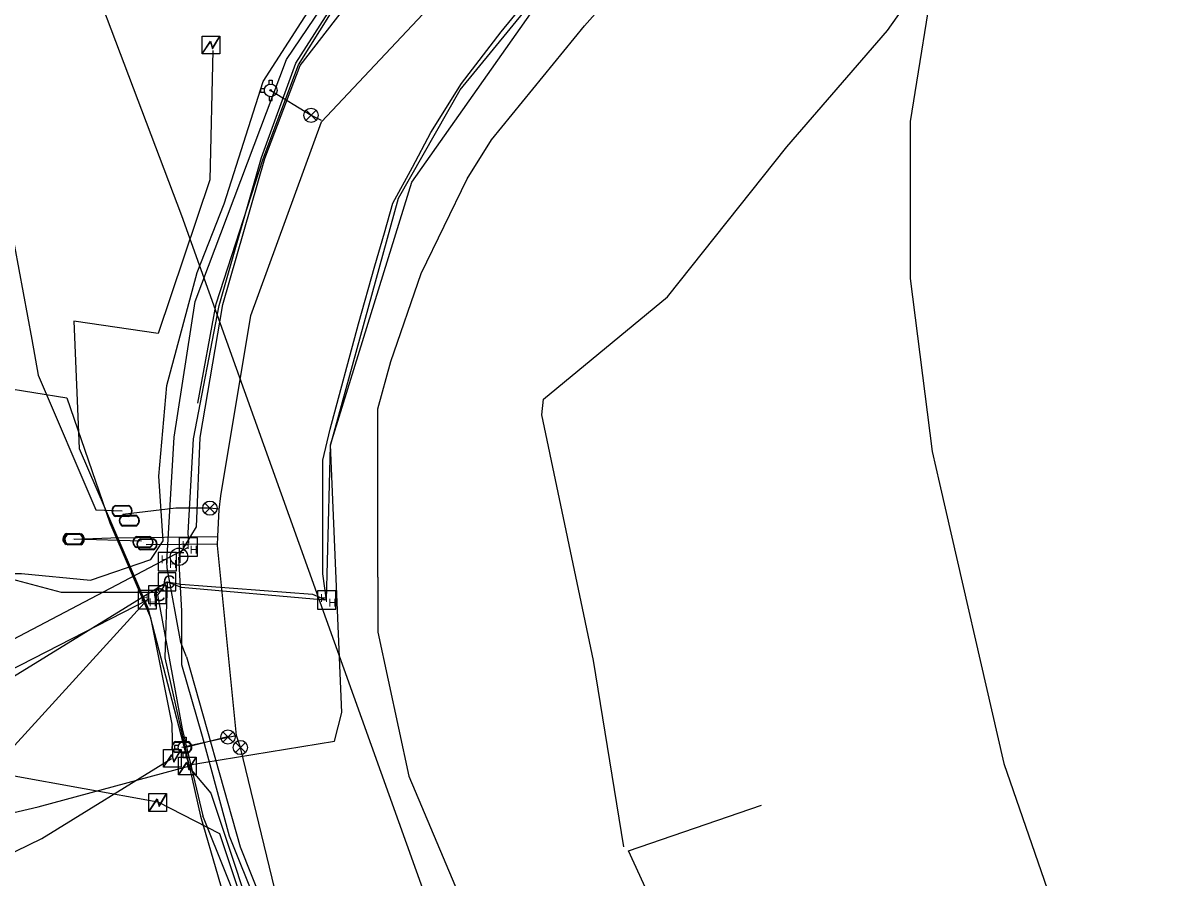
# Model space of a CAD drawing. Extents: x 2070721 to 2083340, y 729290 to 737883.
# Drawn here: x 2080183.4 to 2080544.7, y 734144.7 to 734411.8 of the extents above; entities that cross this region are included whole.
import ezdxf

# ---------------------------------------------------------------- set-up
doc = ezdxf.new("R2010")
doc.units = 0
for name, color, linetype in [('Exist Utilities Other Unknown UG SUE LOS B', 7, 'Continuous'), ('Exist Utilities Power Transformer CELL', 7, 'Continuous'), ('Exist Utilities Power UG Cable SUE LOS B', 7, 'Continuous'), ('Exist Utilities Power UG Cable SUE LOS C', 7, 'Continuous'), ('Exist Utilities Telephone Hand Hole CELL', 7, 'Continuous'), ('Exist Utilities Telephone Manhole CELL', 7, 'Continuous'), ('Exist Utilities Telephone UG Cable SUE LOS C', 7, 'Continuous'), ('Exist Utilities Telephone UG Conduit SUE LOS B', 7, 'Continuous'), ('Exist Utilities Telephone UG FO SUE LOS B', 7, 'Continuous'), ('Exist Utilities Telephone UG FO SUE LOS C', 7, 'Continuous'), ('Exist Utilities TV Hand Hole CELL', 7, 'Continuous'), ('Exist Utilities TV Pedestal CELL', 7, 'Continuous'), ('Exist Utilities TV UG Cable SUE LOS B', 7, 'Continuous'), ('Exist Utilities TV UG Cable SUE LOS C', 7, 'Continuous'), ('Exist Utilities TV UG FO Cable SUE LOS B', 7, 'Continuous'), ('Exist Utilities TV UG FO Cable SUE LOS C', 7, 'Continuous'), ('Exist Utilities Water Fire Hydrant CELL', 7, 'Continuous'), ('Exist Utilities Water Meter CELL', 7, 'Continuous'), ('Exist Utilities Water UG Line SUE LOS B', 7, 'Continuous'), ('Exist Utilities Water Valve CELL', 7, 'Continuous')]:
    doc.layers.add(name, color=color, linetype=linetype)

msp = doc.modelspace()

# ---------------------------------------------------------------- linework, layer by layer
at = {"layer": 'Exist Utilities Other Unknown UG SUE LOS B'}
msp.add_lwpolyline([(2080237.92, 734293.08), (2080243.61, 734324.09), (2080258.34, 734369.36), (2080269.39, 734398.77), (2080286.02, 734425.45), (2080301.91, 734450.14), (2080317.89, 734467.75), (2080331.23, 734480.5), (2080381.43, 734521.31), (2080414.27, 734537.75), (2080416.02, 734538.24)], dxfattribs=at)
at = {"layer": 'Exist Utilities Power Transformer CELL'}
for p, q in [((2080242.08, 734405.14), (2080242.08, 734405.14)), ((2080230.02, 734182.19), (2080230.02, 734182.19)), ((2080234.72, 734179.83), (2080234.72, 734179.83)), ((2080225.45, 734168.4), (2080225.45, 734168.4))]:
    msp.add_line(p, q, dxfattribs=at)
for points in [[(2080239.24, 734407.75), (2080244.79, 734407.75), (2080244.79, 734402.2), (2080239.24, 734402.2)], [(2080227.17, 734184.81), (2080232.73, 734184.81), (2080232.73, 734179.25), (2080227.17, 734179.25)], [(2080231.88, 734182.44), (2080237.43, 734182.44), (2080237.43, 734176.89), (2080231.88, 734176.89)], [(2080222.61, 734171.01), (2080228.16, 734171.01), (2080228.16, 734165.46), (2080222.61, 734165.46)]]:
    msp.add_lwpolyline(points, close=True, dxfattribs=at)
for points in [[(2080239.24, 734402.2), (2080241.88, 734406.14), (2080242.51, 734403.93), (2080244.79, 734407.75)], [(2080239.31, 734402.2), (2080241.88, 734405.93), (2080242.47, 734403.75), (2080244.79, 734407.6)], [(2080227.17, 734179.25), (2080229.82, 734183.2), (2080230.45, 734180.99), (2080232.73, 734184.81)], [(2080227.24, 734179.25), (2080229.82, 734182.99), (2080230.4, 734180.81), (2080232.73, 734184.65)], [(2080231.88, 734176.89), (2080234.52, 734180.84), (2080235.15, 734178.63), (2080237.43, 734182.44)], [(2080231.95, 734176.89), (2080234.52, 734180.63), (2080235.11, 734178.44), (2080237.43, 734182.29)], [(2080222.61, 734165.46), (2080225.25, 734169.4), (2080225.88, 734167.19), (2080228.16, 734171.01)], [(2080222.68, 734165.46), (2080225.25, 734169.19), (2080225.84, 734167.01), (2080228.16, 734170.86)]]:
    msp.add_lwpolyline(points, dxfattribs=at)
at = {"layer": 'Exist Utilities Power UG Cable SUE LOS B'}
for points in [[(2080234.71, 734179.89), (2080280.62, 734187.44), (2080282.92, 734196.34), (2080279.43, 734280.03), (2080304.76, 734362.13), (2080356.55, 734435.67), (2080374.96, 734451.44)], [(2080370.98, 734154.39), (2080361.51, 734212.64), (2080345.43, 734289.41), (2080345.93, 734294.31), (2080384.7, 734326.31), (2080421.96, 734373.11), (2080453.41, 734409.54), (2080468.5, 734430.99)], [(2080468.5, 734430.99), (2080460.53, 734381.1), (2080460.53, 734331.98), (2080467.37, 734277.9), (2080469.6, 734267.89), (2080489.8, 734180.39), (2080505.22, 734135.47), (2080514.45, 734118.41)], [(2080242.66, 734403.28), (2080241.67, 734362.84), (2080225.56, 734314.83), (2080199.19, 734318.7), (2080200.86, 734278.87), (2080222.27, 734229.12), (2080235.32, 734178.97)], [(2080111.69, 734308.48), (2080119.26, 734311.71), (2080135.22, 734307.67), (2080154.56, 734303.8), (2080166.01, 734301.54), (2080176.37, 734298.05), (2080196.98, 734294.69), (2080210.47, 734255.68), (2080223.19, 734226.04), (2080229.85, 734192.73), (2080230.05, 734182.23)], [(2079937.52, 734192.32), (2079957.19, 734181.58), (2080020.32, 734166.12), (2080064.52, 734156.78), (2080106.22, 734147.77), (2080188.06, 734166.87), (2080235.43, 734179.74)], [(2080225.42, 734168.33), (2080179.4, 734176.66), (2080141.16, 734176.91), (2080123.55, 734183.66)], [(2080133.41, 734166.28), (2080133.92, 734165.53), (2080152.74, 734139.3), (2080189.19, 734157.01), (2080229.69, 734182.03)], [(2080234.72, 734179.83), (2080241.98, 734171.12), (2080276.22, 734068.16), (2080293.76, 734026.09), (2080325.21, 734006.15), (2080360.35, 733978.15), (2080376.41, 733964.84), (2080394.21, 733967.31), (2080427.72, 733990.11), (2080441.72, 734003.26), (2080444.29, 734010.08)], [(2080443.09, 734017.91), (2080429.26, 734056.79), (2080388.33, 734118.62), (2080372.45, 734153.12), (2080414.03, 734167.36)]]:
    msp.add_lwpolyline(points, dxfattribs=at)
at = {"layer": 'Exist Utilities Power UG Cable SUE LOS C'}
for points in [[(2080186.05, 734475.29), (2080232.86, 734351.65), (2080379.47, 733942.04), (2080251.03, 733903.89)], [(2080225.45, 734168.4), (2080244.65, 734158.51), (2080253.95, 734130.69), (2080282.75, 734048.52), (2080295.34, 734028.75), (2080340.63, 733997.06), (2080355.06, 733989.84), (2080368.99, 733977.25), (2080380.73, 733968.31), (2080393.86, 733970.13), (2080428.86, 733995.36), (2080444.29, 734010.08)]]:
    msp.add_lwpolyline(points, dxfattribs=at)
at = {"layer": 'Exist Utilities Telephone Hand Hole CELL'}
for p, q in [((2080232.12, 734250.92), (2080232.12, 734245.2)), ((2080237.84, 734250.92), (2080232.12, 734250.92)), ((2080237.84, 734245.2), (2080237.84, 734250.92)), ((2080234.98, 734248.06), (2080234.98, 734248.06)), ((2080225.59, 734246.39), (2080225.59, 734240.67)), ((2080231.31, 734246.39), (2080225.59, 734246.39)), ((2080228.45, 734243.53), (2080228.45, 734243.53)), ((2080231.31, 734240.67), (2080231.31, 734246.39)), ((2080232.12, 734245.2), (2080237.84, 734245.2)), ((2080225.59, 734240.67), (2080231.31, 734240.67)), ((2080219.31, 734234.5), (2080219.31, 734228.77)), ((2080225.03, 734234.5), (2080219.31, 734234.5)), ((2080225.03, 734228.77), (2080225.03, 734234.5)), ((2080219.31, 734228.77), (2080225.03, 734228.77)), ((2080222.17, 734231.63), (2080222.17, 734231.63))]:
    msp.add_line(p, q, dxfattribs=at)
at = {"layer": 'Exist Utilities Telephone Manhole CELL'}
msp.add_circle((2080232.05, 734245.04), 2.72, dxfattribs=at)
at = {"layer": 'Exist Utilities Telephone UG Cable SUE LOS C'}
for points in [[(2080179.48, 734239.75), (2080182.79, 734239.75), (2080204.44, 734237.74), (2080223.27, 734244.14), (2080227.06, 734249.97), (2080225.75, 734270.22), (2080228.23, 734298.53), (2080237.75, 734333.83), (2080246.14, 734355.32), (2080258.39, 734393.6), (2080274.22, 734418.19), (2080320.87, 734477.75), (2080344.36, 734497.56), (2080358.62, 734490.18), (2080387.98, 734454.99)], [(2080294.22, 734238.68), (2080294.22, 734255.9), (2080294.22, 734291.26), (2080298.27, 734306.08), (2080307.66, 734333.57), (2080322.1, 734363.11), (2080329.68, 734375.34), (2080358.78, 734411), (2080382.14, 734437.37), (2080392.23, 734444.72), (2080389.38, 734455.18)], [(2080291.1, 734070.12), (2080273.08, 734096.26), (2080264.86, 734115.07), (2080247.85, 734157.71), (2080239.41, 734188.85), (2080232.9, 734211.26), (2080232.9, 734228.12), (2080231.97, 734244.9)], [(2080294.22, 734238.68), (2080294.22, 734221.46), (2080303.86, 734176.45), (2080326.14, 734123.68), (2080343.11, 734086.02), (2080369.71, 734062.6), (2080410.57, 734039.8), (2080423.78, 734028.65), (2080421.38, 734022.96), (2080402.46, 733993.71), (2080385.13, 733965.19), (2080355.27, 733912.59), (2080339.2, 733870.84), (2080335.53, 733861.67)]]:
    msp.add_lwpolyline(points, dxfattribs=at)
at = {"layer": 'Exist Utilities Telephone UG Conduit SUE LOS B'}
msp.add_lwpolyline([(2080232.24, 734245.67), (2080237.5, 734254.36), (2080238.66, 734282.35), (2080245.75, 734323.83), (2080258.86, 734369.55), (2080269.86, 734398.57), (2080309.08, 734449.32), (2080323.63, 734464.88), (2080355.41, 734492.16), (2080379.52, 734509.8), (2080416.03, 734529.49), (2080502.71, 734562.3), (2080573.96, 734587.12), (2080616.57, 734603.22), (2080677.16, 734624.99), (2080749, 734651.22), (2080815.57, 734674.3), (2080861.11, 734690.56), (2080923.26, 734714.15), (2080934.26, 734720.97)], dxfattribs=at)
at = {"layer": 'Exist Utilities Telephone UG FO SUE LOS B'}
for points in [[(2080235.11, 734249.36), (2080234.94, 734252.48), (2080236.58, 734281.87), (2080244.62, 734323.58), (2080257.8, 734369.84), (2080268.59, 734399.28), (2080285.42, 734425.78), (2080306.49, 734446.52), (2080318.99, 734464.89), (2080332.07, 734479.26), (2080365.28, 734504.24), (2080415, 734536.31), (2080432.75, 734546.34), (2080471.85, 734557.5), (2080502.31, 734568.65), (2080534.18, 734580.2), (2080570.94, 734591.77), (2080576.66, 734593.81), (2080717.24, 734648.01)], [(2080228.28, 734243.43), (2080230.55, 734282.39), (2080237.1, 734324.84), (2080265.61, 734400.42), (2080300.19, 734451.55), (2080329.83, 734482.91), (2080380.99, 734522.11), (2080413.6, 734539.64), (2080433.63, 734544.47), (2080470.56, 734559.5), (2080533.58, 734581.77), (2080652.68, 734625.4)], [(2079959.83, 734188.33), (2080105.23, 734179.43), (2080123.21, 734189.25), (2080234.98, 734248.06)], [(2080234.38, 734213.72), (2080232.6, 734218.25), (2080228.35, 734241.54), (2080228.28, 734243.43)], [(2080234.38, 734213.72), (2080232.6, 734218.25), (2080228.35, 734241.54), (2080228.28, 734243.43)], [(2080222.28, 734231.61), (2080174.53, 734207.04), (2080146.45, 734195)], [(2080234.38, 734213.72), (2080251.15, 734154.39), (2080272, 734101.95), (2080285.47, 734081.3)]]:
    msp.add_lwpolyline(points, dxfattribs=at)
at = {"layer": 'Exist Utilities Telephone UG FO SUE LOS C'}
msp.add_line((2080147.53, 734149.79), (2080222.17, 734231.63), dxfattribs=at)
msp.add_lwpolyline([(2080225.43, 734233.87), (2080195.29, 734233.87), (2080178.12, 734238.44)], dxfattribs=at)
at = {"layer": 'Exist Utilities TV Hand Hole CELL'}
msp.add_line((2080278.21, 734231.5), (2080278.21, 734231.5), dxfattribs=at)
msp.add_lwpolyline([(2080275.34, 734228.63), (2080281.09, 734228.63), (2080281.09, 734234.38), (2080275.34, 734234.38), (2080275.34, 734228.63)], dxfattribs=at)
at = {"layer": 'Exist Utilities TV Pedestal CELL'}
for p, q in [((2080228.33, 734237.2), (2080228.33, 734237.2)), ((2080225.3, 734233.17), (2080225.3, 734233.17))]:
    msp.add_line(p, q, dxfattribs=at)
for points in [[(2080225.55, 734234.43), (2080231.1, 734234.43), (2080231.1, 734239.97), (2080225.55, 734239.97), (2080225.55, 734234.43)], [(2080222.52, 734230.39), (2080228.07, 734230.39), (2080228.07, 734235.94), (2080222.52, 734235.94), (2080222.52, 734230.39)]]:
    msp.add_lwpolyline(points, dxfattribs=at)
at = {"layer": 'Exist Utilities TV UG Cable SUE LOS B'}
for points in [[(2080278.08, 734231.48), (2080277, 734239.67), (2080277, 734275.25), (2080279.3, 734284.9), (2080288.08, 734317.87), (2080293.24, 734335.92), (2080296.25, 734346.26), (2080298.88, 734355.59), (2080304.96, 734366.83), (2080310.77, 734377.58), (2080320.31, 734392.98), (2080332.74, 734409.06), (2080345.11, 734424.32), (2080353.93, 734435.35), (2080365.15, 734446.1), (2080376.65, 734455.86), (2080394.1, 734462.75), (2080415.44, 734468.86), (2080444.8, 734480.86), (2080490.14, 734502.72), (2080540.63, 734520.42), (2080564.59, 734528.02)], [(2080228.33, 734237.2), (2080232.7, 734235.49), (2080277.64, 734231.55)]]:
    msp.add_lwpolyline(points, dxfattribs=at)
at = {"layer": 'Exist Utilities TV UG Cable SUE LOS C'}
msp.add_lwpolyline([(2080228.33, 734237.2), (2080227.59, 734213.41), (2080238.77, 734164.01), (2080249.82, 734126.01), (2080269.26, 734089.95), (2080305.09, 734043.13), (2080320.73, 734021.92)], dxfattribs=at)
at = {"layer": 'Exist Utilities TV UG FO Cable SUE LOS B'}
for points in [[(2080232.67, 734236.44), (2080273.72, 734233.3), (2080278.08, 734231.48), (2080279.38, 734279.77), (2080300.6, 734357.07), (2080319.92, 734390.91), (2080356.3, 734435.5), (2080369.79, 734448.44), (2080390.27, 734462.8), (2080376.9, 734455.01)], [(2080227.31, 734235.69), (2080225.31, 734233.11), (2080233, 734191.29), (2080239.52, 734164.02)], [(2080321.01, 734022.31), (2080305.36, 734043.56), (2080269.25, 734089.82), (2080239.52, 734164.02)]]:
    msp.add_lwpolyline(points, dxfattribs=at)
at = {"layer": 'Exist Utilities TV UG FO Cable SUE LOS C'}
msp.add_lwpolyline([(2079959.93, 734183.76), (2080108.68, 734169.55), (2080152.84, 734190.77), (2080228.33, 734237.2), (2080232.67, 734236.44)], dxfattribs=at)
at = {"layer": 'Exist Utilities Water Fire Hydrant CELL'}
for p, q in [((2080260.69, 734390.79), (2080260.69, 734390.79)), ((2080233.8, 734185.5), (2080233.8, 734185.5))]:
    msp.add_line(p, q, dxfattribs=at)
for points in [[(2080258.78, 734391.3), (2080257.49, 734391.3), (2080257.49, 734390.28), (2080258.78, 734390.28)], [(2080260.18, 734392.7), (2080260.18, 734393.99), (2080261.2, 734393.99), (2080261.2, 734392.68)], [(2080260.18, 734388.88), (2080260.18, 734387.59), (2080261.2, 734387.59), (2080261.2, 734388.9)], [(2080231.89, 734186.01), (2080230.6, 734186.01), (2080230.6, 734184.99), (2080231.89, 734184.99)], [(2080233.29, 734187.41), (2080233.29, 734188.7), (2080234.31, 734188.7), (2080234.31, 734187.39)], [(2080233.29, 734183.59), (2080233.29, 734182.3), (2080234.31, 734182.3), (2080234.31, 734183.61)]]:
    msp.add_lwpolyline(points, dxfattribs=at)
for centre, radius in [((2080260.69, 734390.79), 1.98), ((2080260.69, 734390.79), 0.243), ((2080233.8, 734185.5), 1.98), ((2080233.8, 734185.5), 0.243)]:
    msp.add_circle(centre, radius, dxfattribs=at)
at = {"layer": 'Exist Utilities Water Meter CELL'}
for p, q in [((2080214.25, 734259.36), (2080214.25, 734259.36)), ((2080216.51, 734256.31), (2080216.51, 734256.31)), ((2080198.9, 734250.57), (2080198.9, 734250.57)), ((2080199.4, 734250.49), (2080199.4, 734250.49)), ((2080220.81, 734249.62), (2080220.81, 734249.62)), ((2080222.04, 734248.94), (2080222.04, 734248.94)), ((2080232.95, 734185.55), (2080232.95, 734185.55))]:
    msp.add_line(p, q, dxfattribs=at)
for points in [[(2080216.29, 734257.8), (2080212.19, 734257.8)], [(2080216.29, 734257.66), (2080212.19, 734257.66)], [(2080212.21, 734261.06), (2080216.29, 734261.06)], [(2080212.21, 734260.92), (2080216.29, 734260.92)], [(2080214.47, 734258.01), (2080218.55, 734258.01)], [(2080214.47, 734257.87), (2080218.55, 734257.87)], [(2080218.55, 734254.75), (2080214.45, 734254.75)], [(2080218.55, 734254.61), (2080214.45, 734254.61)], [(2080196.86, 734252.27), (2080200.94, 734252.27)], [(2080196.86, 734252.13), (2080200.94, 734252.13)], [(2080197.36, 734252.19), (2080201.44, 734252.19)], [(2080197.36, 734252.05), (2080201.44, 734252.05)], [(2080218.77, 734251.32), (2080222.84, 734251.32)], [(2080218.77, 734251.18), (2080222.84, 734251.18)], [(2080220, 734250.64), (2080224.08, 734250.64)], [(2080220, 734250.5), (2080224.08, 734250.5)], [(2080200.94, 734249.01), (2080196.84, 734249.01)], [(2080200.94, 734248.87), (2080196.84, 734248.87)], [(2080201.44, 734248.93), (2080197.34, 734248.93)], [(2080201.44, 734248.79), (2080197.34, 734248.79)], [(2080222.84, 734248.06), (2080218.74, 734248.06)], [(2080222.84, 734247.92), (2080218.74, 734247.92)], [(2080224.08, 734247.38), (2080219.98, 734247.38)], [(2080224.08, 734247.24), (2080219.98, 734247.24)], [(2080230.91, 734187.25), (2080234.99, 734187.25)], [(2080230.91, 734187.11), (2080234.99, 734187.11)], [(2080234.99, 734183.99), (2080230.89, 734183.99)], [(2080234.99, 734183.85), (2080230.89, 734183.85)]]:
    msp.add_lwpolyline(points, dxfattribs=at)
for centre, radius, start, end in [((2080212.94, 734259.35), 1.86, 113.178, 245.9794), ((2080212.95, 734259.35), 1.73, 115.3009, 243.7824), ((2080215.2, 734256.3), 1.86, 113.178, 245.9794), ((2080215.22, 734256.3), 1.73, 115.3009, 243.7824), ((2080215.54, 734259.36), 1.86, 293.6483, 66.3084), ((2080215.55, 734259.36), 1.73, 295.1272, 64.8728), ((2080217.8, 734256.31), 1.86, 293.6483, 66.3084), ((2080217.82, 734256.31), 1.73, 295.1272, 64.8728), ((2080197.59, 734250.56), 1.86, 113.178, 245.9794), ((2080197.6, 734250.56), 1.73, 115.3009, 243.7824), ((2080198.09, 734250.48), 1.86, 113.178, 245.9794), ((2080198.1, 734250.48), 1.73, 115.3009, 243.7824), ((2080200.19, 734250.57), 1.86, 293.6483, 66.3084), ((2080200.2, 734250.57), 1.73, 295.1272, 64.8728), ((2080200.69, 734250.49), 1.86, 293.6483, 66.3084), ((2080200.7, 734250.49), 1.73, 295.1272, 64.8728), ((2080219.5, 734249.61), 1.86, 113.178, 245.9794), ((2080219.51, 734249.61), 1.73, 115.3009, 243.7824), ((2080220.73, 734248.93), 1.86, 113.178, 245.9794), ((2080220.74, 734248.93), 1.73, 115.3009, 243.7824), ((2080222.1, 734249.62), 1.86, 293.6483, 66.3084), ((2080222.11, 734249.62), 1.73, 295.1272, 64.8728), ((2080223.33, 734248.94), 1.86, 293.6483, 66.3084), ((2080223.34, 734248.94), 1.73, 295.1272, 64.8728), ((2080231.64, 734185.54), 1.86, 113.178, 245.9794), ((2080231.65, 734185.54), 1.73, 115.3009, 243.7824), ((2080234.24, 734185.55), 1.86, 293.6483, 66.3084), ((2080234.25, 734185.55), 1.73, 295.1272, 64.8728)]:
    msp.add_arc(centre, radius, start, end, dxfattribs=at)
at = {"layer": 'Exist Utilities Water UG Line SUE LOS B'}
for p, q in [((2080199.2, 734250.67), (2080220.33, 734250)), ((2080221.83, 734248.87), (2080243.91, 734249.03)), ((2080233.76, 734185.47), (2080247.2, 734188.81))]:
    msp.add_line(p, q, dxfattribs=at)
for points in [[(2080357.06, 734003.27), (2080353.32, 734006.79), (2080296.63, 734072.2), (2080261.95, 734141.13), (2080251.22, 734185.42), (2080250, 734189.2), (2080244.12, 734248.6), (2080244.13, 734251.5), (2080244.63, 734259.68), (2080245.13, 734264.1), (2080254.44, 734320.44), (2080276.53, 734380.91), (2080391.41, 734503.18), (2080497.9, 734548.7), (2080500.72, 734549.83), (2080585.45, 734578.7), (2080702.53, 734619.89), (2080710.17, 734622.62), (2080743.51, 734634.52), (2080754.26, 734638.28), (2080902.52, 734692.58), (2081024.44, 734735.33)], [(2080260.7, 734390.8), (2080273.35, 734383.02), (2080276.49, 734381.45)], [(2080176.61, 734363.96), (2080186.04, 734312.89), (2080188.09, 734301.77)], [(2080188.09, 734301.77), (2080206.09, 734259.71), (2080214.28, 734259.37)], [(2080214.47, 734258.36), (2080231.01, 734260.34), (2080241.56, 734260.28), (2080244.72, 734260)], [(2080244.2, 734251.31), (2080210.77, 734250.86), (2080199.35, 734250.43)], [(2080232.98, 734185.57), (2080247.35, 734188.69), (2080250.15, 734189.17)]]:
    msp.add_lwpolyline(points, dxfattribs=at)
at = {"layer": 'Exist Utilities Water Valve CELL'}
for points in [[(2080274.88, 734384.58), (2080271.73, 734381.43), (2080273.3, 734383), (2080274.88, 734381.43), (2080271.73, 734384.58)], [(2080243.28, 734261.8), (2080240.12, 734258.65), (2080241.7, 734260.22), (2080243.28, 734258.65), (2080240.12, 734261.8)], [(2080248.92, 734190.28), (2080245.77, 734187.12), (2080247.34, 734188.7), (2080248.92, 734187.12), (2080245.77, 734190.28)], [(2080252.8, 734186.99), (2080249.66, 734183.84), (2080251.23, 734185.42), (2080252.8, 734183.84), (2080249.66, 734186.99)]]:
    msp.add_lwpolyline(points, dxfattribs=at)
for centre in [(2080273.3, 734383), (2080241.7, 734260.22), (2080247.34, 734188.7), (2080251.23, 734185.42)]:
    msp.add_circle(centre, 2.23, dxfattribs=at)

# ---------------------------------------------------------------- texts
at = {"layer": 'Exist Utilities Telephone Hand Hole CELL'}
for p in [(2080232.9, 734247.47), (2080235.47, 734246), (2080226.37, 734242.94), (2080228.94, 734241.47), (2080220.09, 734231.04), (2080222.66, 734229.58)]:
    msp.add_text('H', height=2.5, dxfattribs=at).set_placement(p)
at = {"layer": 'Exist Utilities Telephone Manhole CELL'}
msp.add_text('T', height=3.5, dxfattribs=at).set_placement((2080230.88, 734243.03))
at = {"layer": 'Exist Utilities TV Hand Hole CELL'}
for p in [(2080276.12, 734230.86), (2080278.7, 734229.4)]:
    msp.add_text('H', height=2.5, dxfattribs=at).set_placement(p)
at = {"layer": 'Exist Utilities TV Pedestal CELL'}
for p in [(2080227.02, 734235.2), (2080223.99, 734231.17)]:
    msp.add_text('C', height=4, dxfattribs=at).set_placement(p)

doc.saveas('drawing.dxf')
